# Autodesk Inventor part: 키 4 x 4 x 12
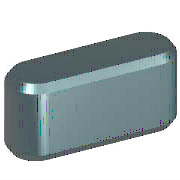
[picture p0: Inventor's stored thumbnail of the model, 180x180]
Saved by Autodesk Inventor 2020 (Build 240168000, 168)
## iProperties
Created: 2012-02
Part Number: 키 4 x 4 x 12
Material: 강철, 연강
Description: 키 및 해당 키홈
Document SubType Name: Modeling
Standard: KS B 1311
Designer: mduedu
Standards Organization: KS
Language: ko-KR
Size Designation: 4 x 4 x 12
Categories: <MemberInstance><Categories><Category DisplayName="샤프트 부품" InternalName="7f7aeb1f-a693-4053-b835-cee3144e0d98" Mnemonic="SHFT"><Category DisplayName="키" Interna
Density: 7.86 g/cm^3
Mass: 1.38739 g
Surface Area: 1.94869 cm^2
Volume: 0.176513 cm^3
Appearance: 노란색
IsCustomPart: 1
Author: mduedu
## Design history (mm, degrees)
workplane "Work Plane1"
workplane "Work Plane2"
sketch "스케치1"
  geometry: L1 (2, 2)-(10, 2); L2 (10, -2)-(2, -2); L3 (0, 9.4)-(0, -7.4) reference; L4 (-5, 0)-(30, 0) reference; L5 (12, 0)-(12, 7); A1 r 2 centre (2, 0) between (2, 2) and (2, -2); A2 r 2 centre (10, 0) between (10, -2) and (10, 2)
  constraints: 6 end point, 5 point on circle, 4 tangent, 3 point on line, 2 centre point, 1 horizontal, 1 parallel, 1 perpendicular
  dimensions: "d0" = 2 radius of A1 (= 0.5 x PB); "d13" = 2 radius of A2 (= 0.5 x PB); "d14" = 12 distance between parallel lines of L5 L3 (= NLG)
extrude "본체1" new body sketch "스케치1" taper "d3" = 0 deg; stored distance "d4" = 10
workplane "Work Plane3"
body "Solid1"
chamfer "모따기1" distance "d8" = 0.25 (= PHH); stored, may be unused: second distance "d9" = 0.25 (= PHH), angle "d15" = 45 deg
other parameters: "d1" = -2.5 (= -PNT), "d2" = 1.5 (= PH - PNT), "NLG" = 12 [user parameter; used in 3 equation terms], "PB" = 4 [user parameter; used in 2 equation terms], "PNT" = 2.5 [user parameter; used in 2 equation terms], "PH" = 4 [user parameter; used in 1 equation term], "PHH" = 0.25 [user parameter; used in 2 equation terms], "d10" = 0, "d16" = 0, "d17" = 0, "d18" = 0, "PLB2" = 12 (= NLG) [user parameter], "WDMAX" = 12 [user parameter], "PLB1" = 12 (= NLG) [user parameter], "RR" = 0.08 [user parameter], "PUEB" = 1.8 [user parameter]
